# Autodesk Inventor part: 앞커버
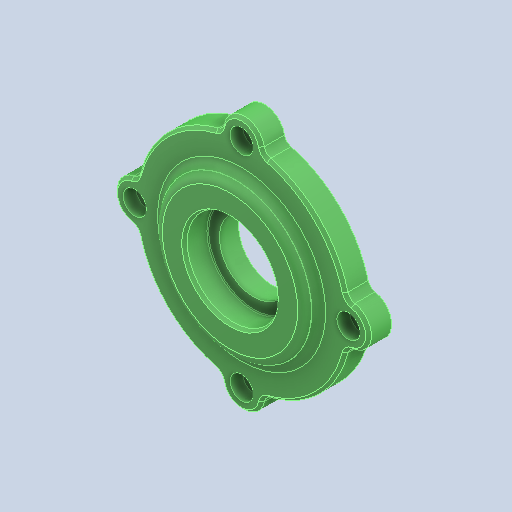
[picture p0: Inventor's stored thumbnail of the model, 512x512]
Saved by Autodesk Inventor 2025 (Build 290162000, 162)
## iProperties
Created: 2025-08
Part Number: 앞커버
Material: 알루미늄 6061
Document SubType Name: Modeling
Designer: infra02
Density: 2.71 g/cm^3
Appearance: 기본값
Company: 한국ATC센터
Author: jhkim
Sending System: Autodesk Inventor 2026
Preprocessor: ST-DEVELOPER v20.1
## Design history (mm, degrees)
feature "솔리드1"
node "솔리드2"
